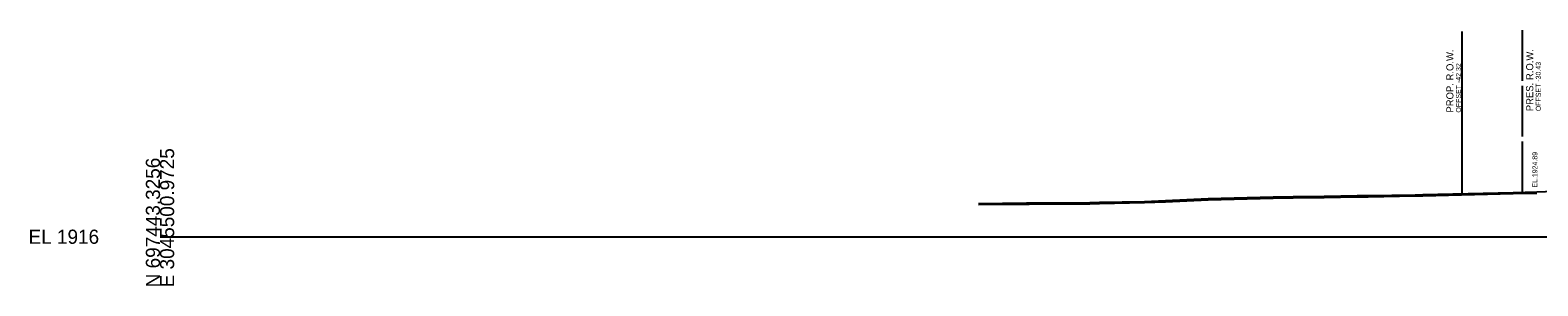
# Model space of a CAD drawing. Extents: x 1574 to 14903, y 7971 to 16537.
# Drawn here: x 14274.3 to 14572.6, y 8490.3 to 8540.8 of the extents above; entities that cross this region are included whole.
import ezdxf

# ---------------------------------------------------------------- set-up
doc = ezdxf.new("R2010")
doc.units = 0
for name, color, linetype in [('DESIGN - ROW - Right-of-Way and Easement Labels', 7, 'Continuous'), ('DESIGN - ROW - Right-of-Way Linework', 7, 'Continuous'), ('DESIGN - SHEET - Light Grid', 7, 'Continuous'), ('DESIGN - TYPICAL - Slope Tie Text', 7, 'Continuous'), ('SURVEY - GROUND - Bottom of Topsoil Layer', 7, 'Continuous'), ('SURVEY - GROUND - Top of Ground', 7, 'Continuous'), ('SURVEY - PROPERTY - ROW Lines', 7, 'Continuous'), ('SURVEY - PROPERTY - ROW Lines Text', 7, 'Continuous')]:
    doc.layers.add(name, color=color, linetype=linetype)

msp = doc.modelspace()

# ---------------------------------------------------------------- linework, layer by layer
at = {"layer": 'DESIGN - ROW - Right-of-Way Linework'}
msp.add_line((14557.68, 8508.52), (14557.68, 8540.52), dxfattribs=at)
at = {"layer": 'DESIGN - SHEET - Light Grid'}
msp.add_line((14300, 8500), (14600, 8500), dxfattribs=at)
at = {"layer": 'SURVEY - GROUND - Bottom of Topsoil Layer'}
for p, q in [((14549.88, 8508.09), (14567.75, 8508.51)), ((14567.75, 8508.51), (14572.42, 8508.6)), ((14461.95, 8506.34), (14471.44, 8506.43)), ((14471.44, 8506.43), (14471.96, 8506.44)), ((14471.96, 8506.44), (14484, 8506.52)), ((14484, 8506.52), (14485.9, 8506.55)), ((14485.9, 8506.55), (14494.83, 8506.74)), ((14494.83, 8506.74), (14498.97, 8506.91)), ((14498.97, 8506.91), (14507.39, 8507.27)), ((14507.39, 8507.27), (14520.26, 8507.6)), ((14520.26, 8507.6), (14524.23, 8507.68)), ((14524.23, 8507.68), (14530.36, 8507.77)), ((14530.36, 8507.77), (14536.86, 8507.87)), ((14536.86, 8507.87), (14539.08, 8507.91)), ((14539.08, 8507.91), (14548.37, 8508.05)), ((14548.37, 8508.05), (14549.88, 8508.09))]:
    msp.add_line(p, q, dxfattribs=at)
at = {"layer": 'SURVEY - GROUND - Top of Ground'}
msp.add_lwpolyline([(14461.95, 8506.59), (14471.44, 8506.68), (14471.96, 8506.69), (14484, 8506.77), (14485.9, 8506.8), (14494.83, 8506.99), (14498.97, 8507.16), (14507.39, 8507.52), (14520.26, 8507.85), (14524.23, 8507.93), (14530.36, 8508.02), (14536.86, 8508.12), (14539.08, 8508.16), (14548.37, 8508.3), (14549.88, 8508.34), (14567.75, 8508.76), (14572.42, 8508.85), (14575.84, 8509.02)], dxfattribs=at)
at = {"layer": 'SURVEY - PROPERTY - ROW Lines'}
for p, q in [((14569.57, 8530.8), (14569.57, 8540.8)), ((14569.57, 8519.8), (14569.57, 8529.8)), ((14569.57, 8508.8), (14569.57, 8518.8))]:
    msp.add_line(p, q, dxfattribs=at)

# ---------------------------------------------------------------- texts
at = {"layer": 'DESIGN - ROW - Right-of-Way and Easement Labels'}
for s, height, p in [('PROP. R.O.W.', 1.4, (14555.93, 8524.52)), ('OFFSET -42.32', 1, (14557.43, 8524.52))]:
    msp.add_text(s, height=height, rotation=90, dxfattribs=at).set_placement(p)
at = {"layer": 'DESIGN - SHEET - Light Grid'}
for s, p in [('E 3045500.9725', (14302.8, 8490)), ('N 697443.3256', (14300, 8490))]:
    msp.add_text(s, height=2.8, rotation=90, dxfattribs=at).set_placement(p)
msp.add_text('EL 1916', height=2.8, dxfattribs=at).set_placement((14274, 8498.6))
at = {"layer": 'DESIGN - TYPICAL - Slope Tie Text'}
msp.add_text('EL.1924.89', height=1, rotation=90, dxfattribs=at).set_placement((14572.54, 8509.69))
at = {"layer": 'SURVEY - PROPERTY - ROW Lines Text'}
for s, height, p in [('PRES. R.O.W.', 1.4, (14571.72, 8524.8)), ('OFFSET -30.43', 1, (14573.22, 8524.8))]:
    msp.add_text(s, height=height, rotation=90, dxfattribs=at).set_placement(p)

doc.saveas('drawing.dxf')
